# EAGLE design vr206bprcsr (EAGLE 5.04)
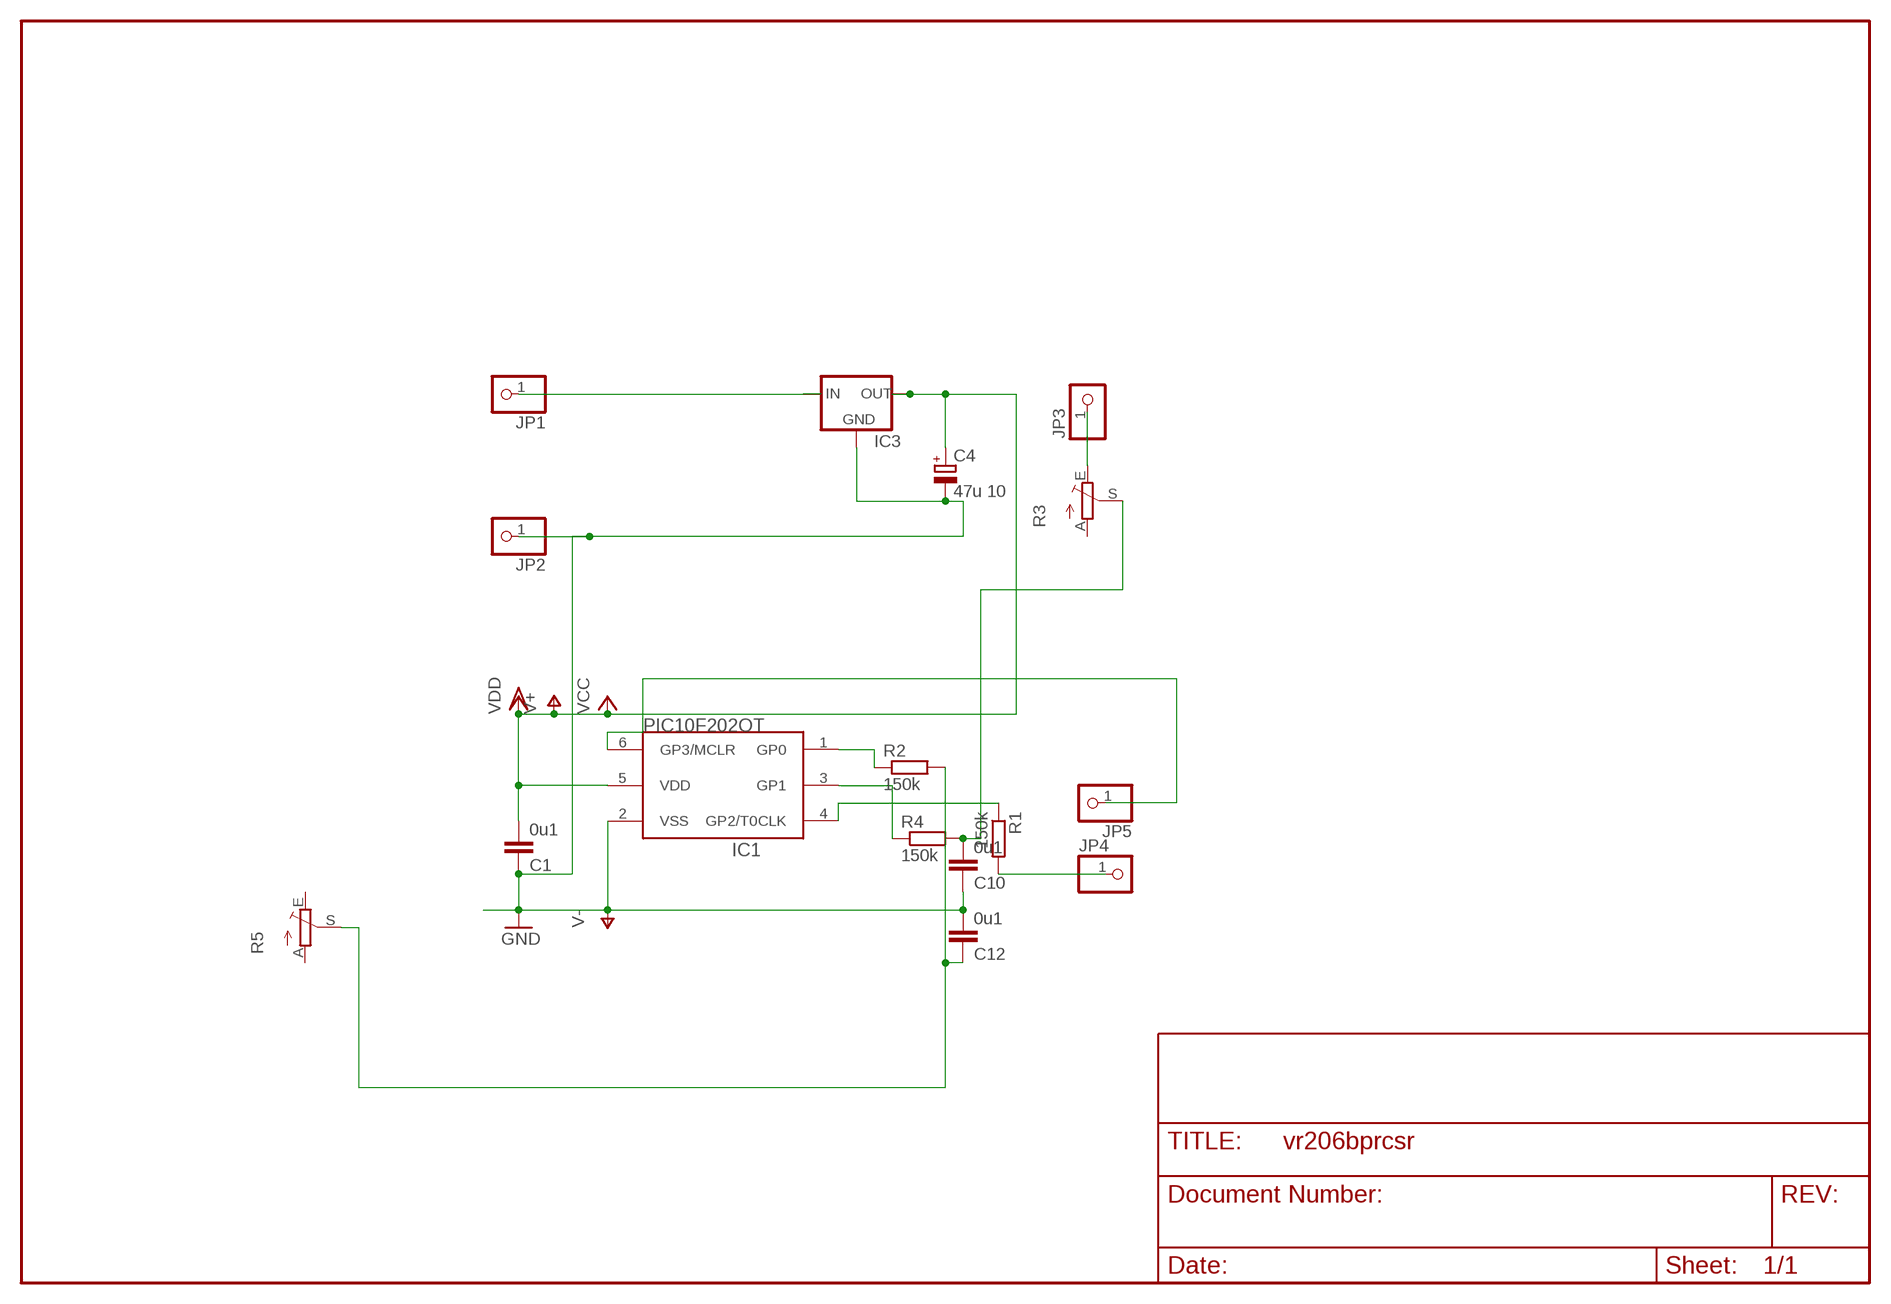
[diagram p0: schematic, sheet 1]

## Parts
C1  0u1  C-EUC1206  [C1206]
C4  47u 10  CPOL-EUE2.5-6  [E2,5-6]
C10  0u1  C-EUC1206  [C1206]
C12  0u1  C-EUC1206  [C1206]
IC1  PIC10F202OT  [SOT23-6]
IC3  78LXX  [78LXX]
JP1  PINHD-1X1  [1X01]
JP2  PINHD-1X1  [1X01]
JP3  PINHD-1X1  [1X01]
JP4  PINHD-1X1  [1X01]
JP5  PINHD-1X1  [1X01]
R1  150k  R-EU_R0805  [R0805]
R2  150k  R-EU_R1206  [R1206]
R3  TRIM_EU-CA6V  [CA6V]
R4  150k  R-EU_R1206  [R1206]
R5  TRIM_EU-CA6V  [CA6V]

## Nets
N$1: JP3.1 R3.E
N$2: JP4.1 R1.2
N$3: IC1.6(GP3/MCLR) JP5.1
N$4: IC1.1(GP0) R2.1
N$5: IC1.4(GP2/T0CLK) R1.1
N$7: IC1.3(GP1) R4.1
N$12: C10.2 R3.S R4.2
N$13: C12.1 R2.2 R5.S
N$20: IC3.IN JP1.1
V+: C1.2 C4.+ IC1.5(VDD) IC3.OUT ; supply symbol labelled VCC, VDD
V-: C1.1 C4.- C10.1 C12.2 IC1.2(VSS) IC3.GND JP2.1 ; supply symbol labelled GND
Unconnected: R3.A R5.A R5.E

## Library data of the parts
C1 C10 C12 = rcl:C-EU: CAPACITOR, European symbol
C4 = rcl:CPOL-EU: POLARIZED CAPACITOR, European symbol
IC1 = microchip-5:PIC10F20*: uPC nW 0,25/0,5k Program Flash memory
IC3 = v-reg:78LXX: VOLTAGE REGULATOR
JP1-JP5 = pinhead:PINHD-1X1: PIN HEADER
R1 R2 R4 = rcl:R-EU_: RESISTOR, European symbol
R3 R5 = pot:TRIM_EU-: POTENTIOMETER

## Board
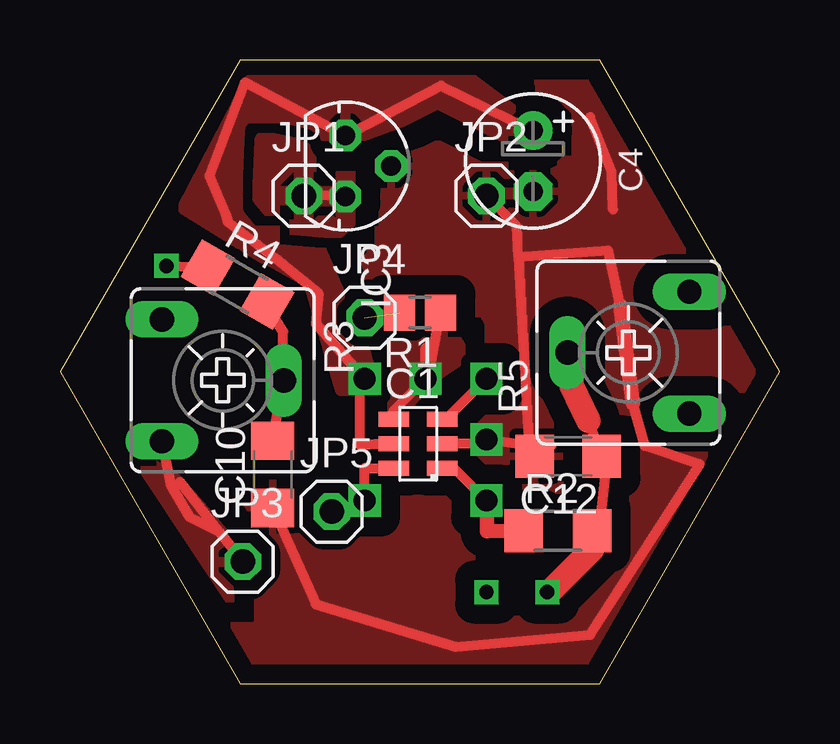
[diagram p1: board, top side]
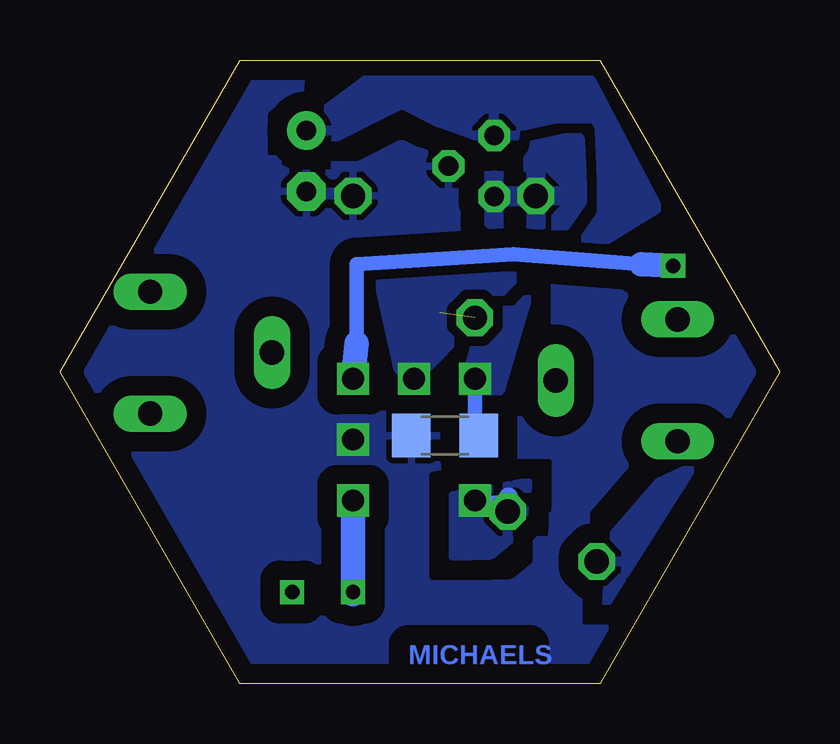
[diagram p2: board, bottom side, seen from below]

Size 30 x 25.98 mm. Coordinates in mm from the lower left corner, seen from the top.
Outline: 7.5,0 22.5,0 30,12.99 22.5,25.98 7.5,25.98 0,12.99 7.5,0
Copper layers (1*16): Top 0.035mm / dielectric 1.5mm / Bottom 0.035mm
Design rules "default *": minimum track width 10mil, minimum drill 24mil, track to track 8mil, track to pad 8mil, pad to pad 8mil, via to via 8mil, smd to smd 8mil, copper to edge 10mil, drill to drill 8mil, minimum pad ring 10mil, minimum via ring 8mil, stop-mask expansion 4mil, vias tented up to drill 0mil, thermal gap 10mil

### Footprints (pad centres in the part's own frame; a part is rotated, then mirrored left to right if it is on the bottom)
C1206 = smd 1.6 x 1.8: 1 -1.4,0; 2 1.4,0
E2,5-6 = drill 0.813 pad 1.6 round: + -1.27,0 | drill 0.813 pad 1.6 octagon: - 1.27,0
SOT23-6 = smd 0.635 x 1.27: 1 -1.016,-1.016; 2 0,-1.016; 3 1.016,-1.016; 4 1.016,1.016; 5 0,1.016; 6 -1.016,1.016
78LXX = drill 0.813 octagon: GND 0,1.905; IN 1.27,0; OUT -1.27,0
1X01 = drill 1.016 octagon: 1 0,0
R0805 = smd 1.3 x 1.5: 1 -0.85,0; 2 0.85,0
R1206 = smd 1.6 x 1.803: 1 -1.422,0; 2 1.422,0
CA6V = drill 1.016 long: A -2.54,-2.54; E 2.54,-2.54; S 0,2.54

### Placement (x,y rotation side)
C1  13.95,10.33 0 bottom
C4  19.72,21.77 270 top
C10  8.87,8.71 90 top
C12  21.19,9.47 180 top
IC1  14.93,9.99 90 top
IC3  11.9,21.56 270 top
JP1  10.16,20.32 0 top
JP2  17.78,20.32 0 top
JP3  7.62,5.08 0 top
JP4  12.7,15.24 0 top
JP5  11.33,7.16 0 top
R1  15.01,15.46 180 top
R2  20.76,6.36 0 top
R3  6.79,12.63 270 top
R4  7.4,16.63 330 top
R5  23.7,13.78 90 top

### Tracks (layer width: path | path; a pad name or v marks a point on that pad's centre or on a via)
N$1
  Top 0.406: 6.63,6.33 5,8.4 | 6.63,6.33 JP3.1 | R3.E 4.62,8.26 5.38,6.95 6.63,6.33
  pour Top (isolate 0.61): 3.02,9.66 7.1,3.5 6.8,6.3 4.9,8.5
  pour Bottom (isolate 0.61): 3.62,9.05 7.2,3.4 6.9,6.2 5,8.4
N$2  (1 unrouted)
N$3  (via drill 0.9)
  Top 0.406: IC1.6 12.7,8.97 v12.7,7.62
  Bottom 0.406: 11.3,7.59 JP5.1 11.33,7.62 v12.7,7.62
  Bottom 0.813: 11.3,7.59 11.3,7.76
  pour Bottom (isolate 0.61): 10.5,8.37 13.6,7.81 13.6,5.31 12.06,5.37 10.75,6.43
N$4  (via drill 0.9)
  Top 0.406: IC1.1 16.43,8.97 v17.78,7.62
  Top 0.61: v17.78,7.62 17.8,6.35 R2.1
  Bottom 0.406: 17.78,3.72 17.8,3.7
  Bottom 1.016: 17.78,3.72 v17.78,7.62
N$5  (via drill 0.9)
  Top 0.406: IC1.4 13.91,11.37 v15.24,12.7 15.24,13.97 15.49,13.72 15.49,13.5 R1.1
  pour Bottom (isolate 0.406): 15.3,12.66 11.16,16.9 15.2,17.1 16.6,16.7 15.8,13.16
  pour Top (isolate 0.406): 15.3,12.66 13.95,11.06 13.98,14.71 16.09,14.92 16.82,13.67
N$7  (via drill 0.6, 0.9)
  Top 0.406: IC1.3 16.09,11.01 v17.78,12.7 | v4.44,17.4 R4.1
  Bottom 0.61: 17.63,14.18 17.64,17.48 11.08,17.9 5.76,17.47
  Bottom 1.016: 17.63,14.18 v17.78,12.7 | v4.44,17.4 5.76,17.47
N$8  (via drill 0.6)
  other vias: 17.78,3.81
N$9  (via drill 0.6)
  other vias: 20.32,3.81
N$12
  Top 0.406: R4.2 8.88,15.34 9.31,14.66 9.31,13.62 R3.S C10.2
N$13
  Top 0.406: 22.18,5.58 R2.2 22.68,6.87 22.53,6.72 22.78,9.02 | 22.78,9.02 C12.1 | 22.78,9.02 22.02,10.95 | 21.31,13.84 R5.S
  Top 1.016: 20.4,3.8 22.18,5.58 | 22.02,10.95 21.31,12.42 21.31,13.84
N$20
  Top 0.406: IC3.IN 10.1,20.38 JP1.1
  pour Top (isolate 0.813): 8.51,22.61 8.41,20.28 9.36,19.12 11.56,18.92 12.06,19.43 12.06,21.34 11.43,21.97
  pour Bottom (isolate 0.813): 8.51,22.61 8.41,20.18 9.06,19.22 11.56,18.92 12.06,19.43 12.06,21.34 11.43,21.97
V+  (via drill 0.9)
  Top 0.406: C4.+ 15.89,24.91 IC3.OUT 7.72,25.05 6.24,21.16 6.9,19.6 7.03,19.2 8.94,17.73 10.79,16.23 10.67,14.99 v12.7,12.7 12.5,12.7 12.5,9.93 13.14,9.99 IC1.5
  Bottom 0.406: 12.7,10.33 C1.2
  Bottom 0.61: v12.7,12.7 12.7,10.33
  pour Top (isolate 0.406, rank 2): 20.32,22.86 17.27,25.15 7.87,25.15 5.08,19.81 10.41,16.51 11.68,12.19 13.21,12.19 12.7,13.97 10.92,18.03 7.37,20.32 8.38,23.37 11.43,22.35 14.22,23.37 15.75,24.13 19.3,22.35
  pour Bottom (isolate 0.406, rank 2): 20.32,22.86 17.27,25.15 7.87,25.15 5.08,19.81 10.41,16.51 11.68,12.19 13.21,12.19 12.7,13.97 10.92,18.03 7.37,20.32 8.38,23.37 11.43,22.35 14.22,23.37 15.75,24.13 19.3,22.35
V-  (via drill 0.9)
  Top 0.406: 23.06,19.75 23,21.3 22.1,23.6 | IC1.2 17.55,9.99 v17.78,10.16 19.56,9.91 | 19.12,17.76 19.56,9.91 | 19.12,17.76 19.05,19.05 JP2.1 | 19.56,9.91 20.48,9.91 C12.2 | C10.1 10.67,3.3 16.51,1.52 22.1,2.03 26.67,9.14 24.38,9.91 23.88,11.68 | 23.37,15.75 22.86,18.03 19.12,17.76
  Top 0.61: 23.88,11.68 23.37,15.75
  pour Top (isolate 0.813, rank 4): 24.94,27.89 28.48,15.48 31.06,13.04 23.09,-1.19 7.34,-0.79 -0.28,14.57 6.46,27.42
  pour Bottom (isolate 0.813, rank 4): 22.4,25.35 31.06,13.04 23.09,-1.19 7.34,-0.79 -0.28,14.57 7.36,26.28

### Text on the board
Bottom: MICHAELS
